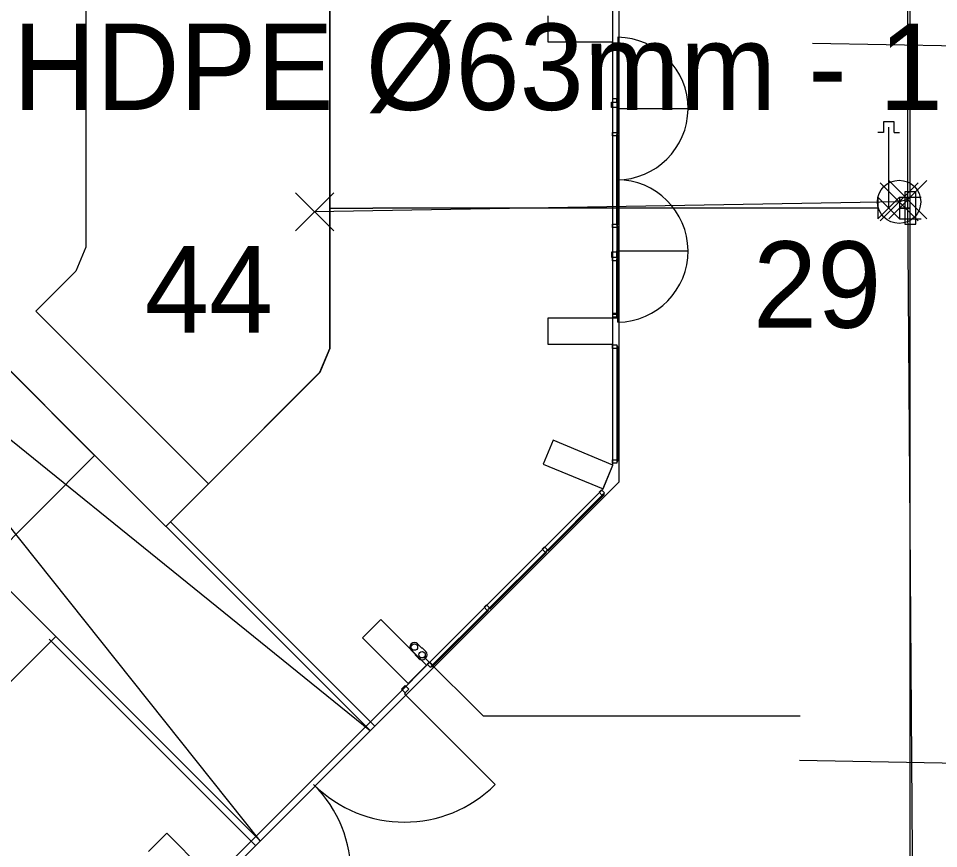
# Model space of a CAD drawing. Extents: x -263964 to -263544, y -1242317 to -1242020.
# Drawn here: x -263808.81 to -263787.49, y -1242235.87 to -1242216.64 of the extents above; entities that cross this region are included whole.
import ezdxf

# ---------------------------------------------------------------- set-up
doc = ezdxf.new("R2010")
doc.units = 0
for name, color, linetype in [('KFA_KOORDINACNA_SITUACIA_DSP_SEDA', 7, 'Continuous'), ('KFA_SO_50-1-II_BODY', 7, 'Continuous'), ('KFA_SO_50-1-II_SUPATKA', 7, 'Continuous'), ('KFA_SO_50-1-II_VODOVODNE_PRIPOJKY', 7, 'Continuous'), ('KFA_SO_50-2_POZIARNY_VODOVOD_TRASA', 7, 'Continuous'), ('POPIS', 7, 'Continuous')]:
    doc.layers.add(name, color=color, linetype=linetype)

msp = doc.modelspace()

# ---------------------------------------------------------------- linework, layer by layer
at = {"layer": 'KFA_KOORDINACNA_SITUACIA_DSP_SEDA'}
for p, q in [((-263788.143, -1242250.14), (-263788.143, -1242082.64)), ((-263795.043, -1242101.769), (-263795.043, -1242226.995)), ((-263807.243, -1242208.394), (-263807.243, -1242221.942)), ((-263801.593, -1242224.282), (-263801.593, -1242208.394)), ((-263796.538, -1242216.582), (-263796.538, -1242217.182)), ((-263795.038, -1242217.182), (-263795.038, -1242216.582)), ((-263796.538, -1242217.182), (-263795.038, -1242217.182)), ((-263794.918, -1242217.077), (-263794.918, -1242218.727)), ((-263795.043, -1242217.282), (-263795.043, -1242217.202)), ((-263795.043, -1242217.202), (-263794.943, -1242217.202)), ((-263795.043, -1242217.282), (-263795.043, -1242217.202)), ((-263795.043, -1242217.202), (-263794.943, -1242217.202)), ((-263794.943, -1242217.282), (-263795.043, -1242217.282)), ((-263794.943, -1242217.282), (-263795.043, -1242217.282)), ((-263794.943, -1242217.202), (-263794.943, -1242217.242)), ((-263794.943, -1242217.202), (-263794.943, -1242217.242)), ((-263794.918, -1242217.212), (-263794.943, -1242217.212)), ((-263794.943, -1242217.212), (-263794.943, -1242219.312)), ((-263794.943, -1242217.242), (-263794.943, -1242217.282)), ((-263794.918, -1242217.242), (-263794.943, -1242217.242)), ((-263794.943, -1242217.242), (-263794.943, -1242218.542)), ((-263794.943, -1242217.242), (-263794.943, -1242217.282)), ((-263794.918, -1242219.312), (-263794.918, -1242217.212)), ((-263794.918, -1242218.542), (-263794.918, -1242217.242)), ((-263781.818, -1242217.375), (-263790.409, -1242217.218)), ((-263795.063, -1242218.702), (-263795.063, -1242218.582)), ((-263795.063, -1242218.582), (-263794.943, -1242218.582)), ((-263794.943, -1242218.502), (-263795.043, -1242218.502)), ((-263795.043, -1242218.502), (-263795.043, -1242218.582)), ((-263795.043, -1242218.582), (-263794.943, -1242218.582)), ((-263794.943, -1242218.542), (-263794.943, -1242218.502)), ((-263794.943, -1242218.542), (-263794.918, -1242218.542)), ((-263794.943, -1242218.582), (-263794.943, -1242218.542)), ((-263794.943, -1242218.582), (-263794.943, -1242218.702)), ((-263794.943, -1242218.702), (-263795.063, -1242218.702)), ((-263794.943, -1242218.702), (-263794.943, -1242218.727)), ((-263794.943, -1242218.727), (-263793.293, -1242218.727)), ((-263788.768, -1242219.032), (-263788.768, -1242219.282)), ((-263788.518, -1242219.032), (-263788.768, -1242219.032)), ((-263788.518, -1242219.282), (-263788.518, -1242219.032)), ((-263795.043, -1242219.362), (-263795.043, -1242219.282)), ((-263795.043, -1242219.282), (-263794.943, -1242219.282)), ((-263794.943, -1242219.282), (-263794.943, -1242219.322)), ((-263794.943, -1242219.312), (-263794.918, -1242219.312)), ((-263788.768, -1242219.282), (-263788.893, -1242219.282)), ((-263788.643, -1242221.032), (-263788.643, -1242219.157)), ((-263788.518, -1242219.282), (-263788.393, -1242219.282)), ((-263794.943, -1242219.362), (-263795.043, -1242219.362)), ((-263794.943, -1242219.322), (-263794.943, -1242219.362)), ((-263794.943, -1242221.432), (-263794.943, -1242219.332)), ((-263794.943, -1242219.332), (-263794.918, -1242219.332)), ((-263794.918, -1242219.332), (-263794.918, -1242221.432)), ((-263788.893, -1242220.782), (-263788.893, -1242221.282)), ((-263788.393, -1242221.282), (-263788.893, -1242220.782)), ((-263788.893, -1242221.282), (-263788.393, -1242220.782)), ((-263788.393, -1242220.782), (-263788.393, -1242221.282)), ((-263788.393, -1242220.782), (-263787.893, -1242220.782)), ((-263788.268, -1242220.657), (-263788.268, -1242221.407)), ((-263788.018, -1242220.657), (-263788.268, -1242220.657)), ((-263788.018, -1242221.407), (-263788.018, -1242220.657)), ((-263801.593, -1242221.032), (-263800.593, -1242221.032)), ((-263788.893, -1242221.032), (-263800.593, -1242221.032)), ((-263788.143, -1242221.032), (-263788.393, -1242221.032)), ((-263788.393, -1242221.032), (-263788.143, -1242221.032)), ((-263795.043, -1242221.482), (-263795.043, -1242221.402)), ((-263795.043, -1242221.402), (-263794.943, -1242221.402)), ((-263794.943, -1242221.402), (-263794.943, -1242221.492)), ((-263794.918, -1242221.432), (-263794.943, -1242221.432)), ((-263788.393, -1242221.282), (-263787.893, -1242221.282)), ((-263788.268, -1242221.407), (-263788.018, -1242221.407)), ((-263794.943, -1242221.482), (-263795.043, -1242221.482)), ((-263794.918, -1242221.452), (-263794.943, -1242221.452)), ((-263794.943, -1242221.452), (-263794.943, -1242223.552)), ((-263794.943, -1242221.492), (-263794.943, -1242221.482)), ((-263794.918, -1242223.552), (-263794.918, -1242221.452)), ((-263807.243, -1242221.942), (-263807.472, -1242222.496)), ((-263794.943, -1242222.052), (-263795.063, -1242222.052)), ((-263795.063, -1242222.052), (-263795.063, -1242222.172)), ((-263794.943, -1242222.052), (-263794.943, -1242222.027)), ((-263794.943, -1242222.027), (-263793.293, -1242222.027)), ((-263794.943, -1242222.172), (-263794.943, -1242222.052)), ((-263794.918, -1242223.677), (-263794.918, -1242222.027)), ((-263795.063, -1242222.172), (-263794.943, -1242222.172)), ((-263795.043, -1242222.252), (-263795.043, -1242222.172)), ((-263795.043, -1242222.172), (-263794.943, -1242222.172)), ((-263794.943, -1242222.252), (-263795.043, -1242222.252)), ((-263794.943, -1242222.172), (-263794.943, -1242222.212)), ((-263794.943, -1242223.512), (-263794.943, -1242222.212)), ((-263794.943, -1242222.212), (-263794.918, -1242222.212)), ((-263794.943, -1242222.212), (-263794.943, -1242222.252)), ((-263794.918, -1242222.212), (-263794.918, -1242223.512)), ((-263807.472, -1242222.496), (-263808.4, -1242223.424)), ((-263808.4, -1242223.424), (-263804.405, -1242227.419)), ((-263795.038, -1242223.582), (-263796.538, -1242223.582)), ((-263796.538, -1242223.582), (-263796.538, -1242224.182)), ((-263794.943, -1242223.472), (-263795.043, -1242223.472)), ((-263795.043, -1242223.472), (-263795.043, -1242223.552)), ((-263794.943, -1242223.497), (-263795.043, -1242223.497)), ((-263795.043, -1242223.497), (-263795.043, -1242223.577)), ((-263795.043, -1242223.552), (-263794.943, -1242223.552)), ((-263795.043, -1242223.577), (-263794.943, -1242223.577)), ((-263795.038, -1242224.182), (-263795.038, -1242223.582)), ((-263794.943, -1242223.512), (-263794.943, -1242223.472)), ((-263794.943, -1242223.537), (-263794.943, -1242223.497)), ((-263794.918, -1242223.512), (-263794.943, -1242223.512)), ((-263794.943, -1242223.552), (-263794.943, -1242223.512)), ((-263794.943, -1242223.577), (-263794.943, -1242223.537)), ((-263794.943, -1242223.552), (-263794.918, -1242223.552)), ((-263796.538, -1242224.182), (-263795.038, -1242224.182)), ((-263795.043, -1242224.282), (-263795.043, -1242224.202)), ((-263795.043, -1242224.202), (-263794.943, -1242224.202)), ((-263794.943, -1242224.202), (-263794.943, -1242224.242)), ((-263801.822, -1242224.837), (-263801.593, -1242224.282)), ((-263794.943, -1242224.282), (-263795.043, -1242224.282)), ((-263794.918, -1242224.242), (-263794.943, -1242224.242)), ((-263794.943, -1242224.242), (-263794.943, -1242226.892)), ((-263794.943, -1242224.242), (-263794.943, -1242224.282)), ((-263794.918, -1242226.892), (-263794.918, -1242224.242)), ((-263804.405, -1242227.419), (-263801.822, -1242224.837)), ((-263796.418, -1242226.411), (-263796.648, -1242226.966)), ((-263795.032, -1242226.985), (-263796.418, -1242226.411)), ((-263796.648, -1242226.966), (-263795.262, -1242227.54)), ((-263795.262, -1242227.54), (-263795.032, -1242226.985)), ((-263795.043, -1242226.945), (-263795.043, -1242226.865)), ((-263795.043, -1242226.865), (-263794.943, -1242226.865)), ((-263794.943, -1242226.945), (-263795.043, -1242226.945)), ((-263794.943, -1242226.865), (-263794.943, -1242226.905)), ((-263794.943, -1242226.892), (-263794.918, -1242226.892)), ((-263794.943, -1242226.905), (-263794.943, -1242226.945)), ((-263795.043, -1242226.995), (-263795.272, -1242227.55)), ((-263795.272, -1242227.55), (-263808.8, -1242241.078)), ((-263795.297, -1242227.56), (-263795.354, -1242227.617)), ((-263795.354, -1242227.617), (-263795.283, -1242227.688)), ((-263795.227, -1242227.631), (-263795.297, -1242227.56)), ((-263795.255, -1242227.659), (-263795.227, -1242227.631)), ((-263796.558, -1242228.963), (-263795.25, -1242227.654)), ((-263795.232, -1242227.672), (-263796.541, -1242228.98)), ((-263795.283, -1242227.688), (-263795.255, -1242227.659)), ((-263795.25, -1242227.654), (-263795.232, -1242227.672)), ((-263805.389, -1242228.403), (-263800.652, -1242233.141)), ((-263805.283, -1242228.297), (-263800.546, -1242233.035)), ((-263796.617, -1242228.879), (-263796.673, -1242228.936)), ((-263796.546, -1242228.95), (-263796.617, -1242228.879)), ((-263796.59, -1242228.994), (-263797.898, -1242230.303)), ((-263797.881, -1242230.32), (-263796.572, -1242229.012)), ((-263796.673, -1242228.936), (-263796.602, -1242229.007)), ((-263796.602, -1242229.007), (-263796.574, -1242228.978)), ((-263796.572, -1242229.012), (-263796.59, -1242228.994)), ((-263796.574, -1242228.978), (-263796.546, -1242228.95)), ((-263796.541, -1242228.98), (-263796.558, -1242228.963)), ((-263797.934, -1242230.338), (-263799.242, -1242231.647)), ((-263799.225, -1242231.664), (-263797.916, -1242230.356)), ((-263797.961, -1242230.223), (-263798.017, -1242230.28)), ((-263798.017, -1242230.28), (-263797.946, -1242230.351)), ((-263797.89, -1242230.294), (-263797.961, -1242230.223)), ((-263797.946, -1242230.351), (-263797.918, -1242230.322)), ((-263797.916, -1242230.356), (-263797.934, -1242230.338)), ((-263797.918, -1242230.322), (-263797.89, -1242230.294)), ((-263797.898, -1242230.303), (-263797.881, -1242230.32)), ((-263800.834, -1242230.985), (-263800.41, -1242230.561)), ((-263800.41, -1242230.561), (-263799.349, -1242231.622)), ((-263808.093, -1242231.016), (-263803.31, -1242235.799)), ((-263807.987, -1242230.91), (-263803.204, -1242235.693)), ((-263799.774, -1242232.046), (-263800.834, -1242230.985)), ((-263799.559, -1242231.13), (-263799.471, -1242231.218)), ((-263799.471, -1242231.218), (-263799.451, -1242231.218)), ((-263799.373, -1242231.296), (-263799.451, -1242231.218)), ((-263799.451, -1242231.218), (-263799.373, -1242231.296)), ((-263799.705, -1242231.275), (-263799.617, -1242231.364)), ((-263799.617, -1242231.364), (-263799.617, -1242231.383)), ((-263799.617, -1242231.383), (-263799.538, -1242231.462)), ((-263799.402, -1242231.432), (-263798.041, -1242232.793)), ((-263799.349, -1242231.622), (-263799.774, -1242232.046)), ((-263799.28, -1242231.543), (-263799.336, -1242231.599)), ((-263799.336, -1242231.599), (-263799.266, -1242231.67)), ((-263799.209, -1242231.613), (-263799.28, -1242231.543)), ((-263799.266, -1242231.67), (-263799.237, -1242231.642)), ((-263799.242, -1242231.647), (-263799.225, -1242231.664)), ((-263799.237, -1242231.642), (-263799.209, -1242231.613)), ((-263799.929, -1242232.178), (-263799.844, -1242232.093)), ((-263799.844, -1242232.093), (-263799.759, -1242232.178)), ((-263799.844, -1242232.263), (-263799.929, -1242232.178)), ((-263799.844, -1242232.263), (-263799.862, -1242232.281)), ((-263799.862, -1242232.281), (-263797.758, -1242234.384)), ((-263799.759, -1242232.178), (-263799.844, -1242232.263)), ((-263798.041, -1242232.793), (-263790.695, -1242232.793)), ((-263781.818, -1242233.99), (-263790.714, -1242233.827)), ((-263805.365, -1242235.516), (-263805.789, -1242235.94)), ((-263804.304, -1242236.576), (-263805.365, -1242235.516))]:
    msp.add_line(p, q, dxfattribs=at)
for points in [[(-263794.893, -1242227.382), (-263808.968, -1242241.457), (-263894.968, -1242241.457), (-263909.043, -1242227.382), (-263909.043, -1242196.333), (-263914.143, -1242196.333), (-263914.143, -1242132.433), (-263909.043, -1242132.433), (-263909.043, -1242101.382), (-263894.968, -1242087.307), (-263808.968, -1242087.307), (-263794.893, -1242101.382), (-263794.893, -1242227.382)], [(-263909.043, -1242125.432), (-263902.343, -1242125.432), (-263902.343, -1242104.482), (-263902.112, -1242103.927), (-263898.54, -1242100.355), (-263895.995, -1242097.81), (-263892.423, -1242094.238), (-263891.868, -1242094.007), (-263812.071, -1242094.007), (-263811.513, -1242094.238), (-263801.823, -1242103.927), (-263801.593, -1242104.482), (-263801.593, -1242224.282), (-263801.824, -1242224.838), (-263805.392, -1242228.407)], [(-263811.918, -1242108.434), (-263811.918, -1242220.33), (-263812.262, -1242220.675), (-263809.862, -1242221.669), (-263810.999, -1242222.806), (-263807.039, -1242226.765), (-263809.585, -1242229.311), (-263813.545, -1242225.351), (-263814.681, -1242226.488), (-263815.675, -1242224.088), (-263816.02, -1242224.432), (-263887.916, -1242224.432)], [(-263807.941, -1242230.956), (-263813.544, -1242225.352), (-263814.681, -1242226.488), (-263815.675, -1242224.088), (-263812.262, -1242220.675)], [(-263812.262, -1242220.675), (-263809.863, -1242221.669), (-263810.999, -1242222.806), (-263805.392, -1242228.407)], [(-263803.204, -1242235.693), (-263813.559, -1242222.704), (-263800.652, -1242233.141)], [(-263807.942, -1242230.956), (-263811.512, -1242234.526), (-263812.068, -1242234.757), (-263891.868, -1242234.757), (-263892.424, -1242234.526), (-263895.994, -1242230.956)]]:
    msp.add_lwpolyline(points, dxfattribs=at)
msp.add_lwpolyline([(-263801.593, -1242208.394), (-263807.243, -1242208.394), (-263807.243, -1242221.942), (-263807.472, -1242222.496), (-263808.4, -1242223.424), (-263804.405, -1242227.419), (-263801.822, -1242224.837), (-263801.593, -1242224.282)], close=True, dxfattribs=at)
for centre in [(-263799.632, -1242231.202), (-263799.455, -1242231.379)]:
    msp.add_circle(centre, 0.075, dxfattribs=at)
for centre, radius, start, end in [((-263794.943, -1242218.727), 1.65, 270, 89.1318), ((-263794.943, -1242222.027), 1.65, 270.8682, 90), ((-263799.632, -1242231.202), 0.103, 45, 225), ((-263799.455, -1242231.379), 0.117, 225, 45), ((-263804.069, -1242236.488), 2.975, 315.0001, 45.0001), ((-263799.862, -1242232.281), 2.975, 224.9999, 314.9999)]:
    msp.add_arc(centre, radius, start, end, dxfattribs=at)
at = {"layer": 'KFA_SO_50-1-II_BODY'}
for p, q in [((-263788.844, -1242221.33), (-263787.96, -1242220.446)), ((-263787.96, -1242221.33), (-263788.844, -1242220.446)), ((-263788.644, -1242221.279), (-263787.76, -1242220.395)), ((-263787.76, -1242221.279), (-263788.644, -1242220.395)), ((-263802.385, -1242221.561), (-263801.501, -1242220.677)), ((-263801.501, -1242221.561), (-263802.385, -1242220.677))]:
    msp.add_line(p, q, dxfattribs=at)
at = {"layer": 'KFA_SO_50-1-II_SUPATKA'}
msp.add_circle((-263788.402, -1242220.888), 0.5, dxfattribs=at)
at = {"layer": 'KFA_SO_50-1-II_VODOVODNE_PRIPOJKY'}
msp.add_lwpolyline([(-263788.202, -1242220.837), (-263788.402, -1242220.888), (-263801.943, -1242221.119)], dxfattribs=at)
at = {"layer": 'KFA_SO_50-2_POZIARNY_VODOVOD_TRASA'}
msp.add_lwpolyline([(-263924.479, -1242117.427), (-263924.931, -1242185.127), (-263924.146, -1242197.091), (-263924.185, -1242203.3), (-263924.296, -1242220.899), (-263924.1, -1242250.121), (-263913.986, -1242249.798), (-263886.91, -1242249.876), (-263867.714, -1242249.83), (-263837.257, -1242249.836), (-263828.162, -1242249.901), (-263787.99, -1242250.032), (-263788.202, -1242220.837), (-263788.195, -1242200.509), (-263788.092, -1242179.915), (-263788.062, -1242148.958), (-263787.919, -1242127.952)], dxfattribs=at)

# ---------------------------------------------------------------- texts
at = {"layer": 'KFA_SO_50-1-II_BODY'}
for s, p in [('29', (-263791.788, -1242223.804)), ('44', (-263805.879, -1242223.915))]:
    msp.add_text(s, height=2, dxfattribs=at).set_placement(p)
at = {"layer": 'POPIS'}
msp.add_text('HDPE Ø63mm - 13,75m', height=2, dxfattribs=at).set_placement((-263808.935, -1242218.76))

doc.saveas('drawing.dxf')
